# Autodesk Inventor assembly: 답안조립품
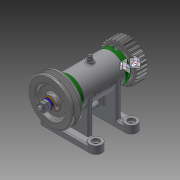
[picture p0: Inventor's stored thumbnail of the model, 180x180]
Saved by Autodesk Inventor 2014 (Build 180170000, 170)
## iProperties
Created: 2015-11
Part Number: 답안조립품
Document SubType Name: Assembly
Designer: basic
Author: basic
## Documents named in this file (16)
- C:\Users\basic\Desktop\451110V1025\답안조립품.iam
- C:\Users\basic\Desktop\451110V1025\본체.ipt
- C:\Users\basic\Desktop\451110V1025\축.ipt
- C:\Users\basic\Desktop\451110V1025\키 3 x 3 x 12.ipt
- C:\Users\basic\Desktop\451110V1025\스퍼기어.ipt
- C:\Users\basic\Desktop\451110V1025\스프링와셔 8.ipt
- C:\Users\basic\Desktop\451110V1025\와셔 8x17.ipt
- C:\Users\basic\Desktop\451110V1025\너트 M 8.ipt
- C:\Users\basic\Desktop\451110V1025\커버.ipt
- C:\Users\basic\Desktop\451110V1025\베어링 15 x 32 x 9.ipt
- C:\Users\basic\Desktop\451110V1025\오일 실 15 25 7.ipt
- C:\Users\basic\Desktop\451110V1025\볼트 M4 x 12.ipt
- C:\Users\basic\Desktop\451110V1025\V벨트풀리.ipt
- C:\Users\basic\Desktop\451110V1025\니플 M 6 x 0.75.ipt
- C:\Users\basic\Desktop\451110V1025\볼트 M 6 x 8.ipt
- C:\Users\basic\Desktop\451110V1025\와셔 6x11.5.ipt
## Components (11 placed, 3 different names)
1. KS B 2023 6002 - 15 x 32 x 9:1
2. KS B 2023 6002 - 15 x 32 x 9:2
3. ISO 4762 M4 x 12:1
4. ISO 4762 M4 x 12:2
5. ISO 4762 M4 x 12:3
6. ISO 4762 M4 x 12:4
7. ISO 4762 M4 x 12:5
8. ISO 4762 M4 x 12:6
9. ISO 4762 M4 x 12:7
10. ISO 4762 M4 x 12:8
11. V벨트풀리:1
